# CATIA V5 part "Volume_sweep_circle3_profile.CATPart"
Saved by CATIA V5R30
Part number: Part1
Bounding box of the stored display mesh (mm): x -210.021 to 26.553, y 0 to 145.736, z -54.983 to 55
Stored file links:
  D:\PROJECTS\CATIA V56R 2020\Resources\Parts File\c17_catia_v6_6r2020_prt\Volume_sweep_circle3_profile.CATPart
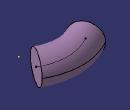
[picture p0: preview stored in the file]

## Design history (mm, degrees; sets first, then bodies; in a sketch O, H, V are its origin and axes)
Set1
  Sketch1 on xy-plane, origin (0, 0, 0), H (1, 0, 0), V (0, 1, 0)
    line L1 (0, 0) -> (-183.1008, 0)
    horizontal: L1 H
  Sketch2 on xy-plane, origin (0, 0, 0), H (1, 0, 0), V (0, 1, 0)
    spline S1 through (0, 65.5148) (-89.6654, 90.7245) (-183.6013, 65.5148)
    point P1 (0, 65.5148)
    coincidence: P1 V
  Sweep1: type Circle, Guide Sketch2, Radius 55
Body1 (main body)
